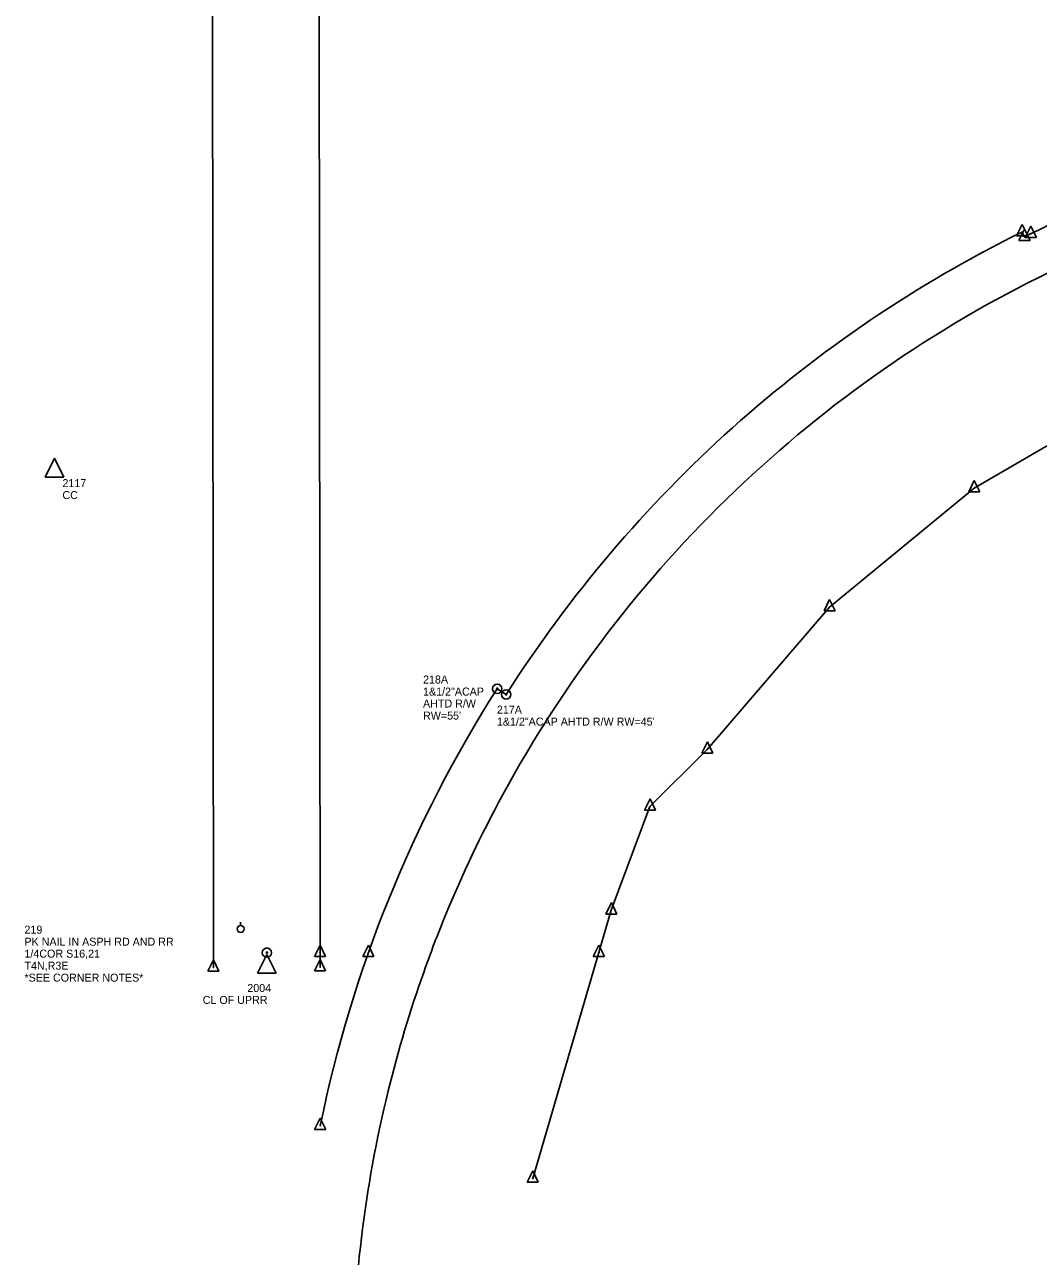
# Model space of a CAD drawing. Extents: x 1674300 to 1677920, y 225056 to 231852.
# Drawn here: x 1674467 to 1675417, y 226211 to 227365 of the extents above; entities that cross this region are included whole.
import ezdxf

# ---------------------------------------------------------------- set-up
doc = ezdxf.new("R2010")
doc.units = 0
for name, color, linetype in [('S_CAL_CORNER', 7, 'Continuous'), ('S_CAL_CORNER_ANNOT', 7, 'Continuous'), ('S_EXIST_ROW', 7, 'Continuous'), ('S_EXISTING_ALIGNMENT', 7, 'Continuous'), ('S_IRON_PIN', 7, 'Continuous'), ('S_IRON_PIN_ANNOT', 7, 'Continuous'), ('S_UTILITY_POLE', 7, 'Continuous')]:
    doc.layers.add(name, color=color, linetype=linetype)

msp = doc.modelspace()

# ---------------------------------------------------------------- linework, layer by layer
at = {"layer": 'S_CAL_CORNER'}
for p, q in [((1674494.9, 226958.8), (1674486.1, 226941.1)), ((1674494.9, 226958.8), (1674503.6, 226941.1)), ((1674486.1, 226941.1), (1674503.6, 226941.1)), ((1674693.9, 226493.7), (1674685.1, 226476)), ((1674693.9, 226493.7), (1674702.6, 226476)), ((1674685.1, 226476), (1674702.6, 226476))]:
    msp.add_line(p, q, dxfattribs=at)
at = {"layer": 'S_EXIST_ROW'}
for p, q in [((1674743.8, 226481.8), (1674738.5, 231819.6)), ((1674643.8, 226481.7), (1674642.5, 227834.3)), ((1675410, 227169.4), (1675740.5, 227330.2)), ((1675401.7, 227178), (1675396.5, 227167.4)), ((1675404, 227173.5), (1675398.7, 227162.9)), ((1675401.7, 227178), (1675407, 227167.4)), ((1675401.7, 227170.9), (1675401.7, 227170.9)), ((1675401.7, 227170.9), (1675403.9, 227166.4)), ((1675404, 227173.5), (1675409.2, 227162.9)), ((1675410, 227176.5), (1675404.7, 227165.9)), ((1675410, 227176.5), (1675415.2, 227165.9)), ((1675410, 227169.4), (1675410, 227169.4)), ((1675396.5, 227167.4), (1675407, 227167.4)), ((1675398.7, 227162.9), (1675409.2, 227162.9)), ((1675403.9, 227166.4), (1675403.9, 227166.4)), ((1675404.7, 227165.9), (1675415.2, 227165.9)), ((1675357, 226930.8), (1675488.7, 227007.5)), ((1675221.3, 226819.2), (1675357, 226930.8)), ((1675357, 226937.9), (1675351.7, 226927.3)), ((1675351.7, 226927.3), (1675362.3, 226927.3)), ((1675357, 226937.9), (1675362.3, 226927.3)), ((1675357, 226930.8), (1675357, 226930.8)), ((1675221.3, 226826.3), (1675216.1, 226815.7)), ((1675221.3, 226826.3), (1675226.6, 226815.7)), ((1675106.8, 226686), (1675221.3, 226819.2)), ((1675216.1, 226815.7), (1675226.6, 226815.7)), ((1675221.3, 226819.2), (1675221.3, 226819.2)), ((1674909.8, 226742.8), (1674918.2, 226737.4)), ((1675053, 226632.4), (1675106.8, 226686)), ((1675106.8, 226693.1), (1675101.5, 226682.5)), ((1675106.8, 226693.1), (1675112, 226682.5)), ((1675106.8, 226686), (1675106.8, 226686)), ((1675101.5, 226682.5), (1675112, 226682.5)), ((1675053.1, 226639.5), (1675047.8, 226628.9)), ((1675053.1, 226639.5), (1675058.3, 226628.9)), ((1675016.7, 226535.2), (1675053, 226632.4)), ((1675047.8, 226628.9), (1675058.3, 226628.9)), ((1675053, 226632.4), (1675053, 226632.4)), ((1674943.1, 226283.7), (1675016.7, 226535.2)), ((1675016.8, 226542.3), (1675011.5, 226531.6)), ((1675016.7, 226535.2), (1675016.7, 226535.2)), ((1675016.8, 226542.3), (1675022, 226531.6)), ((1675011.5, 226531.6), (1675022, 226531.6)), ((1674743.8, 226502.5), (1674738.5, 226491.9)), ((1674743.8, 226502.5), (1674749, 226491.9)), ((1674789.1, 226502.5), (1674783.8, 226491.9)), ((1674789.1, 226502.5), (1674794.3, 226491.9)), ((1675005.1, 226502.5), (1674999.8, 226491.9)), ((1675005.1, 226502.5), (1675010.3, 226491.9)), ((1674643.8, 226488.8), (1674638.5, 226478.1)), ((1674643.8, 226488.8), (1674649, 226478.1)), ((1674738.5, 226491.9), (1674749, 226491.9)), ((1674743.8, 226488.9), (1674738.5, 226478.2)), ((1674743.8, 226495.4), (1674743.8, 226495.4)), ((1674743.8, 226488.9), (1674749, 226478.2)), ((1674783.8, 226491.9), (1674794.3, 226491.9)), ((1674789.1, 226495.4), (1674789.1, 226495.4)), ((1674999.8, 226491.9), (1675010.3, 226491.9)), ((1675005.1, 226495.4), (1675005.1, 226495.4)), ((1674638.5, 226478.1), (1674649, 226478.1)), ((1674643.8, 226481.7), (1674643.8, 226481.7)), ((1674738.5, 226478.2), (1674749, 226478.2)), ((1674743.8, 226481.8), (1674743.8, 226481.8)), ((1674744, 226340.3), (1674738.7, 226329.7)), ((1674744, 226340.3), (1674749.2, 226329.7)), ((1674738.7, 226329.7), (1674749.2, 226329.7)), ((1674743.9, 226333.2), (1674743.9, 226333.2)), ((1674943.1, 226290.8), (1674937.8, 226280.2)), ((1674937.8, 226280.2), (1674948.3, 226280.2)), ((1674943.1, 226290.8), (1674948.3, 226280.2)), ((1674943.1, 226283.7), (1674943.1, 226283.7))]:
    msp.add_line(p, q, dxfattribs=at)
for centre, radius in [((1675401.7, 227170.9), 0.18), ((1675401.7, 227170.9), 0.09), ((1675410, 227169.4), 0.18), ((1675410, 227169.4), 0.09), ((1675403.9, 227166.4), 0.18), ((1675403.9, 227166.4), 0.09), ((1675357, 226930.8), 0.18), ((1675357, 226930.8), 0.09), ((1675221.3, 226819.2), 0.18), ((1675221.3, 226819.2), 0.09), ((1675106.8, 226686), 0.18), ((1675106.8, 226686), 0.09), ((1675053, 226632.4), 0.18), ((1675053, 226632.4), 0.09), ((1675016.7, 226535.2), 0.18), ((1675016.7, 226535.2), 0.09), ((1674743.8, 226495.4), 0.18), ((1674743.8, 226495.4), 0.09), ((1674789.1, 226495.4), 0.18), ((1674789.1, 226495.4), 0.09), ((1675005.1, 226495.4), 0.18), ((1675005.1, 226495.4), 0.09), ((1674643.8, 226481.7), 0.18), ((1674643.8, 226481.7), 0.09), ((1674743.8, 226481.8), 0.18), ((1674743.8, 226481.8), 0.09), ((1674743.9, 226333.2), 0.18), ((1674743.9, 226333.2), 0.09), ((1674943.1, 226283.7), 0.18), ((1674943.1, 226283.7), 0.09)]:
    msp.add_circle(centre, radius, dxfattribs=at)
for radius, start, end in [(1206.4, 116.2645, 147.493), (1201.4, 115.9436, 116.2645), (1216.4, 147.493, 168.4201)]:
    msp.add_arc((1675935.6, 226089.1), radius, start, end, dxfattribs=at)
at = {"layer": 'S_EXISTING_ALIGNMENT'}
for start, end in [(115.9436, 151.516), (151.516, 157.6885), (157.6885, 160.4451), (160.4451, 166.2144), (166.2144, 180.0564)]:
    msp.add_arc((1675935.6, 226089.1), 1161.4, start, end, dxfattribs=at)
at = {"layer": 'S_IRON_PIN'}
for centre, radius in [((1674909.8, 226742.8), 4.36), ((1674909.8, 226742.8), 0.617), ((1674909.8, 226742.8), 0.392), ((1674909.8, 226742.8), 0.317), ((1674909.8, 226742.8), 0.218), ((1674909.8, 226742.8), 0.123), ((1674909.8, 226742.8), 0.0872), ((1674918.2, 226737.4), 4.36), ((1674918.2, 226737.4), 0.617), ((1674918.2, 226737.4), 0.392), ((1674918.2, 226737.4), 0.317), ((1674918.2, 226737.4), 0.218), ((1674918.2, 226737.4), 0.0872), ((1674918.2, 226737.4), 0.123), ((1674693.9, 226495.4), 4.36), ((1674693.9, 226495.4), 0.617), ((1674693.9, 226495.4), 0.392), ((1674693.9, 226495.4), 0.317), ((1674693.9, 226495.4), 0.218), ((1674693.9, 226495.4), 0.123), ((1674693.9, 226495.4), 0.0872)]:
    msp.add_circle(centre, radius, dxfattribs=at)
at = {"layer": 'S_UTILITY_POLE'}
msp.add_line((1674669.1, 226520.8), (1674669.1, 226524), dxfattribs=at)
msp.add_circle((1674669.3, 226517.6), 3.19, dxfattribs=at)

# ---------------------------------------------------------------- texts
at = {"layer": 'S_CAL_CORNER_ANNOT'}
for s, p in [('2117', (1674502.3, 226931.8)), ('CC', (1674502.3, 226920.6)), ('2004', (1674675.6, 226458.5)), ('CL OF UPRR', (1674633.8, 226447.3))]:
    msp.add_text(s, height=7.5, rotation=360, dxfattribs=at).set_placement(p)
at = {"layer": 'S_IRON_PIN_ANNOT'}
for s, p in [('218A', (1674840.3, 226747.7)), ('1&1/2"ACAP', (1674840.3, 226736.4)), ('AHTD R/W', (1674840.3, 226725.2)), ("RW=55'", (1674840.3, 226713.9)), ('217A', (1674909.5, 226719.4)), ('1&1/2"ACAP AHTD R/W RW=45\'', (1674909.5, 226708.2)), ('219', (1674466.7, 226513.2)), ('PK NAIL IN ASPH RD AND RR ', (1674466.7, 226501.9)), ('1/4COR S16,21', (1674466.7, 226490.7)), ('T4N,R3E', (1674466.7, 226479.4)), ('*SEE CORNER NOTES*', (1674466.7, 226468.2))]:
    msp.add_text(s, height=7.5, rotation=360, dxfattribs=at).set_placement(p)

doc.saveas('drawing.dxf')
